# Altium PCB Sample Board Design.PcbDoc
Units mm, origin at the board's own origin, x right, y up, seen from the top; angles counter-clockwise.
Board outline 8.4 x 9.9 mm, 2 copper layers (Top Layer, Bottom Layer); 1 components, 0 nets, 3 pads, 0 vias.
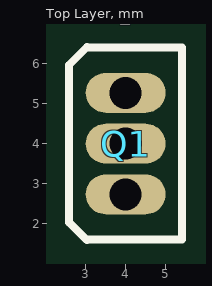
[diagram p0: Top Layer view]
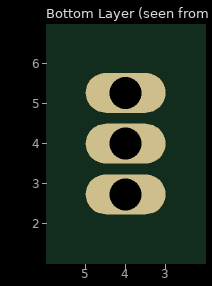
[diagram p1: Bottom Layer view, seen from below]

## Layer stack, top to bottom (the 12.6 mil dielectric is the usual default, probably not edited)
Top Solder: solder mask 0.0102, Solder Resist, Dk 3.5
Top Layer: signal copper 0.0356
Dielectric 1: dielectric 0.32, FR-4, Dk 4.8
Bottom Layer: signal copper 0.0356
Bottom Solder: solder mask 0.0102, Solder Resist, Dk 3.5

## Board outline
0,0 8.4,0 8.4,9.9 0,9.9

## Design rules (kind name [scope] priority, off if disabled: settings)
AssemblyTestPointUsage [All] p0: scope1count=1 scope1_0_kind=Board scope1_0_value=Board scope2count=1 scope2_0_kind=Board scope2_0_value=Board commentlength=0
AssemblyTestpoint [All] p0: scope1count=1 scope1_0_kind=Board scope1_0_value=Board scope2count=1 scope2_0_kind=Board scope2_0_value=Board commentlength=0
Clearance [All] p0: scope1count=1 scope1_0_kind=Board scope1_0_value=Board scope2count=1 scope2_0_kind=Board scope2_0_value=Board commentlength=0 gap=0.254
Clearance [All] p1: gap=0.254 ignorepadtopadclearanceinfootprint=FALSE except(0: Arc-Hole Track-Hole SMDPad-Hole THPad-Hole Via-Hole Fill-Hole Poly-Hole Region-Hole Text-Hole)
ComponentClearance [All] p0: scope1count=1 scope1_0_kind=Board scope1_0_value=Board scope2count=1 scope2_0_kind=Board scope2_0_value=Board commentlength=0 gap=0.254 collisioncheckmode=3
DiffPairsRouting [All] p0: scope1count=1 scope1_0_kind=Board scope1_0_value=Board scope2count=1 scope2_0_kind=Board scope2_0_value=Board commentlength=0
FabricationTestPointUsage [All] p0: scope1count=1 scope1_0_kind=Board scope1_0_value=Board scope2count=1 scope2_0_kind=Board scope2_0_value=Board commentlength=0 valid=0 allowmultiple=FALSE
FabricationTestpoint [All] p0: scope1count=1 scope1_0_kind=Board scope1_0_value=Board scope2count=1 scope2_0_kind=Board scope2_0_value=Board commentlength=0 side=3 testpointundercomponent=TRUE minsize=1.016 maxsize=2.54 preferedsize=1.524 minholesize=0 maxholesize=1.016 preferedholesize=0.813 testpointgrid=0.025
FanoutControl Fanout_BGA [All] p0 off: scope1count=1 scope1_0_kind=Board scope1_0_value=Board scope2count=1 scope2_0_kind=Board scope2_0_value=Board commentlength=69 // Protel DXP Scope 1 Expression Was: IsBGA   Fanout_BGA (Default Rule)
FanoutControl Fanout_LCC [All] p0 off: scope1count=1 scope1_0_kind=Board scope1_0_value=Board scope2count=1 scope2_0_kind=Board scope2_0_value=Board commentlength=69 // Protel DXP Scope 1 Expression Was: IsLCC   Fanout_LCC (Default Rule)
FanoutControl Fanout_SOIC [All] p0 off: scope1count=1 scope1_0_kind=Board scope1_0_value=Board scope2count=1 scope2_0_kind=Board scope2_0_value=Board commentlength=71 // Protel DXP Scope 1 Expression Was: IsSOIC   Fanout_SOIC (Default Rule)
FanoutControl Fanout_Small [All] p0 off: scope1count=1 scope1_0_kind=Board scope1_0_value=Board scope2count=1 scope2_0_kind=Board scope2_0_value=Board commentlength=84 // Protel DXP Scope 1 Expression Was: (CompPinCount < 5)   Fanout_Small (Default Rule)
FanoutControl Fanout_Default [All] p0: scope1count=1 scope1_0_kind=Board scope1_0_value=Board scope2count=1 scope2_0_kind=Board scope2_0_value=Board commentlength=30 // Fanout_Default (Default Rule)
Height [All] p0: scope1count=1 scope1_0_kind=Board scope1_0_value=Board scope2count=1 scope2_0_kind=Board scope2_0_value=Board commentlength=0
HoleSize [All] p0: scope1count=1 scope1_0_kind=Board scope1_0_value=Board scope2count=1 scope2_0_kind=Board scope2_0_value=Board commentlength=0 absolutevalues=TRUE maxlimit=2.54 minlimit=0.025 maxpercent=80.000 minpercent=20.000
HoleToHoleClearance [All] p0: scope1count=1 scope1_0_kind=Board scope1_0_value=Board scope2count=1 scope2_0_kind=Board scope2_0_value=Board commentlength=0
LayerPairs [All] p0: scope1count=1 scope1_0_kind=Board scope1_0_value=Board scope2count=1 scope2_0_kind=Board scope2_0_value=Board commentlength=0 enforce=TRUE
MinimumSolderMaskSliver [All] p0: scope1count=1 scope1_0_kind=Board scope1_0_value=Board scope2count=1 scope2_0_kind=Board scope2_0_value=Board commentlength=0
NetAntennae [All] p0: scope1count=1 scope1_0_kind=Board scope1_0_value=Board scope2count=1 scope2_0_kind=Board scope2_0_value=Board commentlength=0
PasteMaskExpansion [All] p0: scope1count=1 scope1_0_kind=Board scope1_0_value=Board scope2count=1 scope2_0_kind=Board scope2_0_value=Board commentlength=0 expansion=0
PlaneClearance [All] p0: scope1count=1 scope1_0_kind=Board scope1_0_value=Board scope2count=1 scope2_0_kind=Board scope2_0_value=Board commentlength=0 clearance=0.508
PlaneConnect [All] p0: scope1count=1 scope1_0_kind=Board scope1_0_value=Board scope2count=1 scope2_0_kind=Board scope2_0_value=Board commentlength=0 planeconnectstyle=Relief reliefexpansion=0.508 reliefentries=4 reliefconductorwidth=0.254 reliefairgap=0.254
PolygonConnect [All] p0: scope1count=1 scope1_0_kind=Board scope1_0_value=Board scope2count=1 scope2_0_kind=Board scope2_0_value=Board commentlength=0 connectstyle=Relief reliefconductorwidth=0.254 reliefentries=4 polygonreliefangle="90 Angle"
PolygonConnect [All] p1: connectstyle=Relief reliefconductorwidth=0.254 reliefentries=4 polygonreliefangle="90 Angle" airgapwidth=0.254
RoutingCorners [All] p0: scope1count=1 scope1_0_kind=Board scope1_0_value=Board scope2count=1 scope2_0_kind=Board scope2_0_value=Board commentlength=0 cornerstyle=45-Degree minsetback=2.54 maxsetback=2.54
RoutingLayers [All] p0: scope1count=1 scope1_0_kind=Board scope1_0_value=Board scope2count=1 scope2_0_kind=Board scope2_0_value=Board commentlength=0 top layer=Automatic bottom layer=Automatic
RoutingPriority [All] p0: scope1count=1 scope1_0_kind=Board scope1_0_value=Board scope2count=1 scope2_0_kind=Board scope2_0_value=Board commentlength=0
RoutingTopology [All] p0: scope1count=1 scope1_0_kind=Board scope1_0_value=Board scope2count=1 scope2_0_kind=Board scope2_0_value=Board commentlength=0 topology=Shortest
RoutingVias [All] p0: scope1count=1 scope1_0_kind=Board scope1_0_value=Board scope2count=1 scope2_0_kind=Board scope2_0_value=Board commentlength=0 holewidth=0.711 width=1.27 viastyle="Through Hole" minholewidth=0.711 minwidth=1.27 maxholewidth=0.711 maxwidth=1.27
RoutingVias [All] p1: holewidth=0.711 width=1.27 viastyle="Through Hole" minholewidth=0.711 minwidth=1.27 maxholewidth=0.711 maxwidth=1.27
ShortCircuit [All] p0: scope1count=1 scope1_0_kind=Board scope1_0_value=Board scope2count=1 scope2_0_kind=Board scope2_0_value=Board commentlength=0 allowed=FALSE
SilkToBoardRegionClearance [All] p0: scope1count=1 scope1_0_kind=Board scope1_0_value=Board scope2count=1 scope2_0_kind=Board scope2_0_value=Board commentlength=0
SilkToSilkClearance [All] p0: scope1count=1 scope1_0_kind=Board scope1_0_value=Board scope2count=1 scope2_0_kind=Board scope2_0_value=Board commentlength=0
SilkToSolderMaskClearance [All] p0 off: scope1count=1 scope1_0_kind=Board scope1_0_value=Board scope2count=1 scope2_0_kind=Board scope2_0_value=Board commentlength=44 // Protel DXP Scope 1 Expression Was: IsPad
SolderMaskExpansion [All] p0: scope1count=1 scope1_0_kind=Board scope1_0_value=Board scope2count=1 scope2_0_kind=Board scope2_0_value=Board commentlength=0 expansion=0.102
SolderMaskExpansion [All] p1: expansion=0.102
UnRoutedNet [All] p0: scope1count=1 scope1_0_kind=Board scope1_0_value=Board scope2count=1 scope2_0_kind=Board scope2_0_value=Board commentlength=0
UnpouredPolygon [All] p0: scope1count=1 scope1_0_kind=Board scope1_0_value=Board scope2count=1 scope2_0_kind=Board scope2_0_value=Board commentlength=0
Width [All] p0: scope1count=1 scope1_0_kind=Board scope1_0_value=Board scope2count=1 scope2_0_kind=Board scope2_0_value=Board commentlength=0 maxlimit=0.254 minlimit=0.254 preferedwidth=0.254
Width [All] p1: maxlimit=0.254 minlimit=0.254 preferedwidth=0.254
30 further rules are at their usual default settings.

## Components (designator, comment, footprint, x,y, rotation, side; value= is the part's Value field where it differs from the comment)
Q1 "" E3 4,4 r0 top

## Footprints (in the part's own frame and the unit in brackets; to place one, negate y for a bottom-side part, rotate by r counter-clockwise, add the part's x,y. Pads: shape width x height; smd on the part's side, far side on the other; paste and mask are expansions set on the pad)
E3 [mm]
  oval 2x1 hole 0.8: 1(0,1.27) 2(0,0) 3(0,-1.27)
  silkscreen extent -1.41,-2.41 1.41,2.41

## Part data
Q1: library part MOSFET-N, "N-Channel MOSFET"

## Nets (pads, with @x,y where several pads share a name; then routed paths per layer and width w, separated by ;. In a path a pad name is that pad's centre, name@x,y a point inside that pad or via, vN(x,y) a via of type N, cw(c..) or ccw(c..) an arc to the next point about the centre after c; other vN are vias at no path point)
pads on no net: Q1.1 Q1.2 Q1.3

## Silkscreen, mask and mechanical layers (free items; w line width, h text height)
Mechanical 1:
  the board outline again, w0.254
